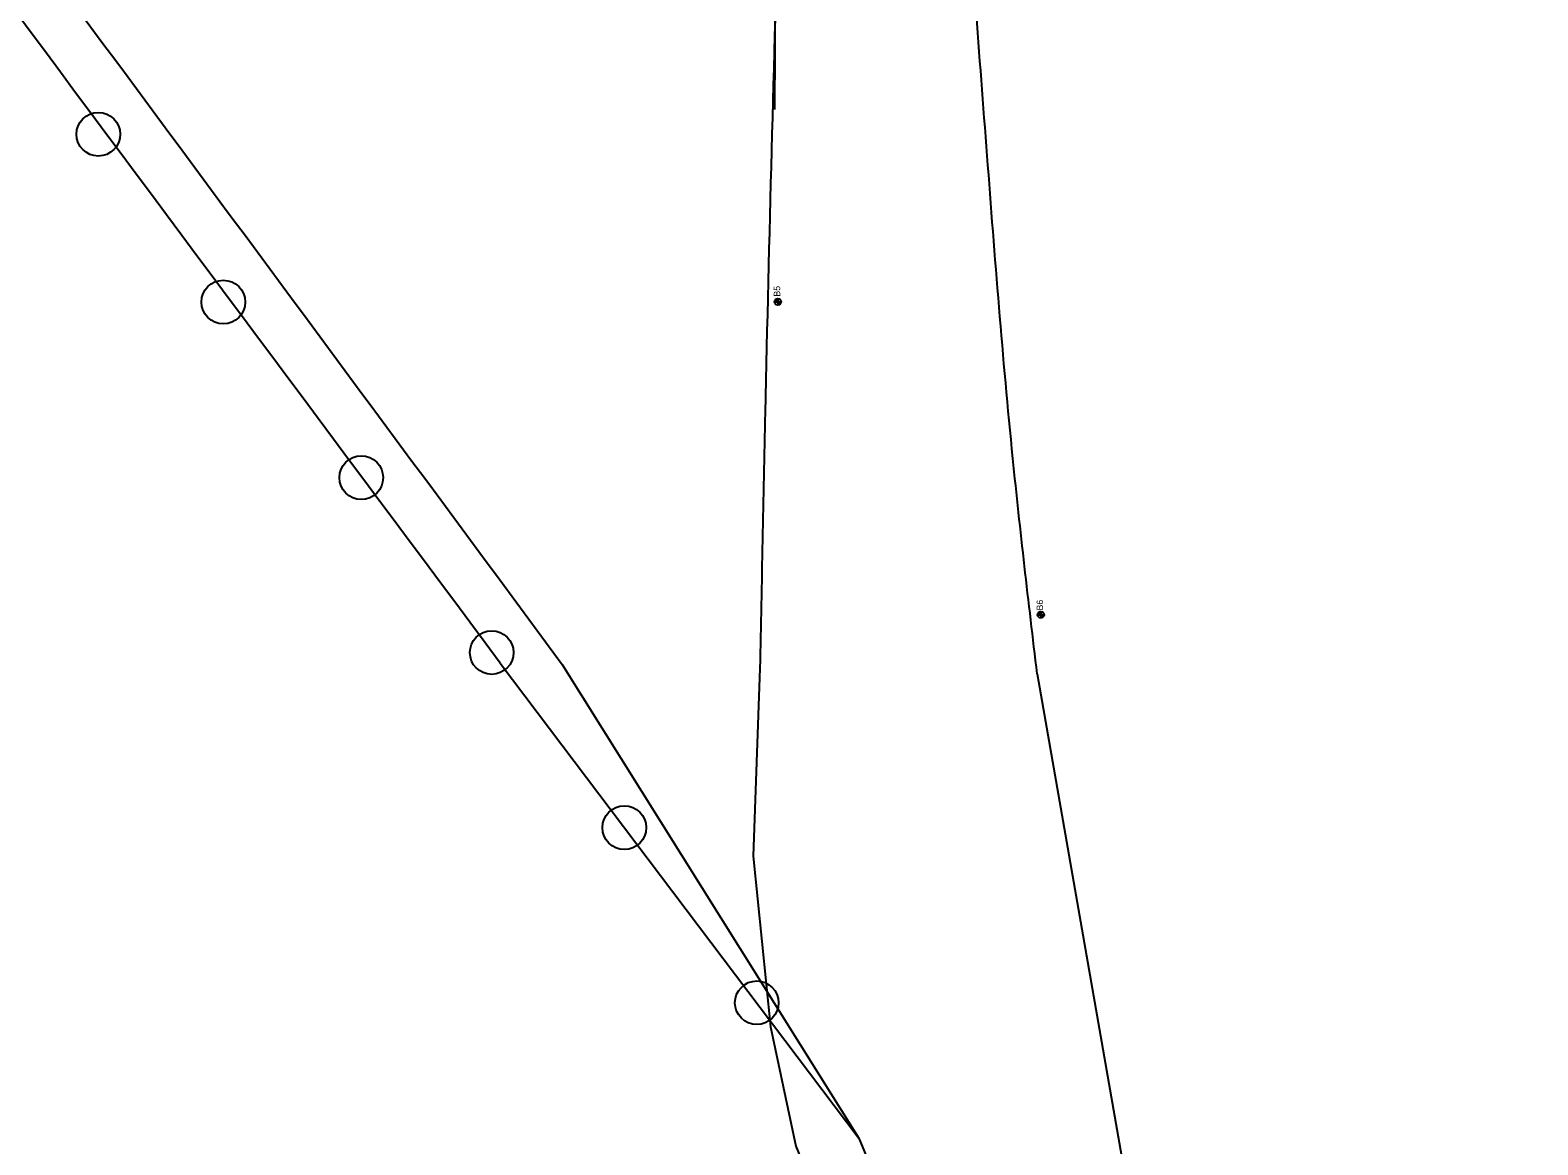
# Model space of a CAD drawing. Extents: x 331323 to 388339, y 121519 to 205315.
# Drawn here: x 360253 to 362567, y 129507 to 131218 of the extents above; entities that cross this region are included whole.
import ezdxf

# ---------------------------------------------------------------- set-up
doc = ezdxf.new("R2010")
doc.units = 0
for name, color, linetype in [('CE-TOPO-CONC-SLAB', 7, 'Continuous'), ('E_SOIL_BORE2 [KAPUR_CADDS_LEVELS]', 7, 'Continuous'), ('Level 2', 7, 'Continuous'), ('P_MARK', 7, 'Continuous')]:
    doc.layers.add(name, color=color, linetype=linetype)

msp = doc.modelspace()

# ---------------------------------------------------------------- linework, layer by layer
at = {"layer": 'CE-TOPO-CONC-SLAB'}
for centre in [(360357.8, 131058), (360549.6, 130800.4), (360761.3, 130530.9), (360961.5, 130262.4), (361164.9, 129993.6), (361368.2, 129724.8)]:
    msp.add_circle(centre, 33.5, dxfattribs=at)
at = {"layer": 'Level 2'}
for p in [(360974.7, 130246.3), (361069.7, 130244.3)]:
    msp.add_line(p, (361524.8, 129516.9), dxfattribs=at)
for points in [[(361373.1, 130238.2), (361362.5, 129949.9), (361389.4, 129688.1), (361428.3, 129504.5), (361563.5, 129175.9)], [(361798.4, 130229.7), (361947.9, 129375.8), (362175.7, 128517.9), (362415.7, 127734.4), (362566.7, 127294.1)], [(361524.8, 129516.9), (361674, 129156.9), (361920.1, 128489.2), (362093.1, 127949.7), (362303.7, 127294.9)]]:
    msp.add_lwpolyline(points, dxfattribs=at)
for points in [[(360974.7, 130246.3), (359488.5, 132249.8), (358879.2, 133079.6), (357889.3, 134411.1), (357444.5, 134981.1), (357256, 135199.5), (355476.6, 136957.3)], [(355623.7, 136961.1), (356920.4, 135674.4), (357158.4, 135427.5), (357273.3, 135300.2), (357385.4, 135170.3), (357696.2, 134781.1), (358305.3, 133973.7), (358998.6, 133039.4), (360249.6, 131353.3), (361069.7, 130244.3)], [(361798.4, 130229.7), (361761.2, 130560.4), (361721.8, 131024.9), (361686.5, 131489.7), (361651.5, 131954.5), (361613, 132419.1), (361458.1, 134102), (361264.2, 136436.9), (361242.2, 136715.1)], [(361414.2, 133749.5), (361447, 133280.1), (361431.6, 132242.1), (361381, 130630.3), (361373.1, 130238.2)], [(361158.4, 133317.4), (361306.9, 132849), (361382.9, 132387.7), (361394.4, 132057.6), (361395.5, 131096.1)]]:
    msp.add_spline(points, degree=3, dxfattribs=at)
at = {"layer": 'P_MARK'}
for p, q in [((361400.5, 130805.6), (361400.5, 130795.6)), ((361395.5, 130800.6), (361405.5, 130800.6)), ((361799, 130320.5), (361809, 130320.5)), ((361804, 130325.5), (361804, 130315.5))]:
    msp.add_line(p, q, dxfattribs=at)
for centre in [(361400.5, 130800.6), (361804, 130320.5)]:
    msp.add_circle(centre, 5, dxfattribs=at)
for centre, radius, start, end in [((361400.5, 130800.6), 4.5, 89.9869, 179.9869), ((361400.5, 130800.6), 4, 89.9869, 179.9869), ((361400.5, 130800.6), 3.5, 89.9869, 179.9869), ((361400.5, 130800.6), 3, 89.9869, 179.9869), ((361400.5, 130800.6), 2.5, 89.9869, 179.9869), ((361400.5, 130800.6), 2, 89.9869, 179.9869), ((361400.5, 130800.6), 1.5, 89.9869, 179.9869), ((361400.5, 130800.6), 1, 89.9869, 179.9869), ((361400.5, 130800.6), 0.5, 89.9869, 179.9869), ((361400.5, 130800.6), 4.5, 269.9869, 359.9869), ((361400.5, 130800.6), 4, 269.9869, 359.9869), ((361400.5, 130800.6), 3.5, 269.9869, 359.9869), ((361400.5, 130800.6), 3, 269.9869, 359.9869), ((361400.5, 130800.6), 2.5, 269.9869, 359.9869), ((361400.5, 130800.6), 2, 269.9869, 359.9869), ((361400.5, 130800.6), 1.5, 269.9869, 359.9869), ((361400.5, 130800.6), 1, 269.9869, 359.9869), ((361400.5, 130800.6), 0.5, 269.9869, 359.9869), ((361804, 130320.5), 4.5, 89.9869, 179.9869), ((361804, 130320.5), 4, 89.9869, 179.9869), ((361804, 130320.5), 3.5, 89.9869, 179.9869), ((361804, 130320.5), 3, 89.9869, 179.9869), ((361804, 130320.5), 2.5, 89.9869, 179.9869), ((361804, 130320.5), 2, 89.9869, 179.9869), ((361804, 130320.5), 1.5, 89.9869, 179.9869), ((361804, 130320.5), 1, 89.9869, 179.9869), ((361804, 130320.5), 0.5, 89.9869, 179.9869), ((361804, 130320.5), 4.5, 269.9869, 359.9869), ((361804, 130320.5), 4, 269.9869, 359.9869), ((361804, 130320.5), 3.5, 269.9869, 359.9869), ((361804, 130320.5), 3, 269.9869, 359.9869), ((361804, 130320.5), 2.5, 269.9869, 359.9869), ((361804, 130320.5), 2, 269.9869, 359.9869), ((361804, 130320.5), 1.5, 269.9869, 359.9869), ((361804, 130320.5), 1, 269.9869, 359.9869), ((361804, 130320.5), 0.5, 269.9869, 359.9869)]:
    msp.add_arc(centre, radius, start, end, dxfattribs=at)

# ---------------------------------------------------------------- texts
at = {"layer": 'E_SOIL_BORE2 [KAPUR_CADDS_LEVELS]'}
for s, p in [('B5', (361404.2, 130808.8)), ('B6', (361807.5, 130327))]:
    msp.add_text(s, height=10, rotation=89.9869, dxfattribs=at).set_placement(p)

doc.saveas('drawing.dxf')
